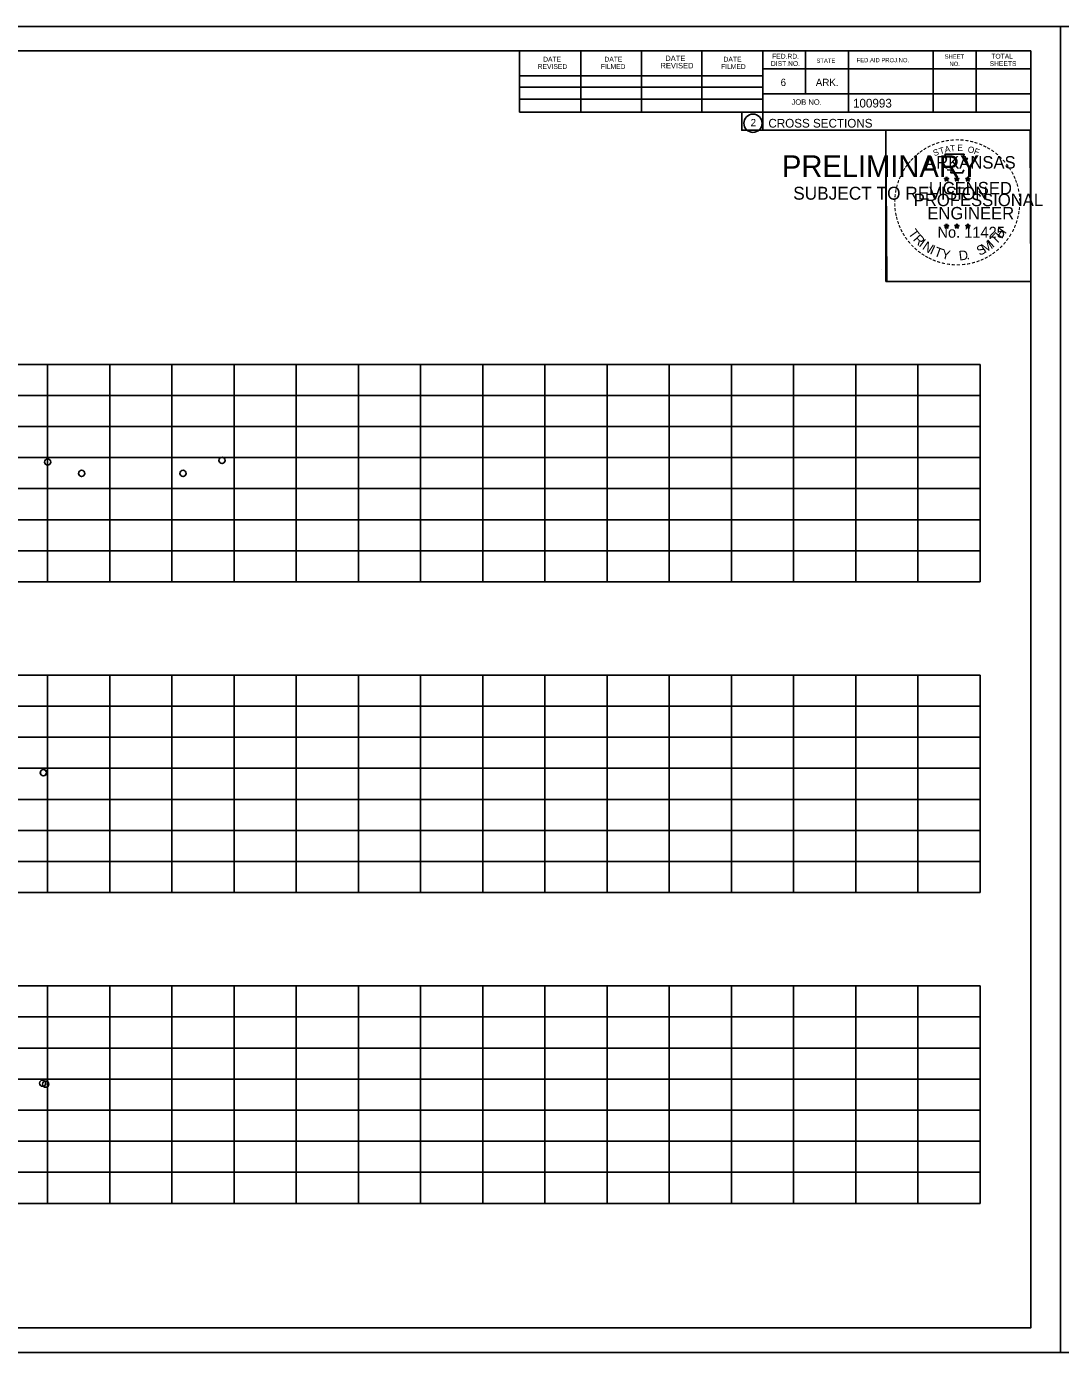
# Model space of a CAD drawing. Extents: x 4667 to 1632277, y -2100 to 724501.
# Drawn here: x 6136.1 to 6302.5, y -1963.8 to -1750.4 of the extents above; entities that cross this region are included whole.
import ezdxf

# ---------------------------------------------------------------- set-up
doc = ezdxf.new("R2010")
doc.units = 0
doc.layers.add('R_Grid', color=7, linetype='Continuous')
doc.layers.add('R_No Plot', color=7, linetype='Continuous')

msp = doc.modelspace()

# ---------------------------------------------------------------- linework, layer by layer
at = {"layer": 'R_Grid'}
for p, q in [((5989.52, -1804.78), (6289.52, -1804.78)), ((6139.52, -1839.78), (6139.52, -1804.78)), ((6149.52, -1839.78), (6149.52, -1804.78)), ((6159.52, -1839.78), (6159.52, -1804.78)), ((6169.52, -1839.78), (6169.52, -1804.78)), ((6179.52, -1839.78), (6179.52, -1804.78)), ((6189.52, -1839.78), (6189.52, -1804.78)), ((6199.52, -1839.78), (6199.52, -1804.78)), ((6209.52, -1839.78), (6209.52, -1804.78)), ((6219.52, -1839.78), (6219.52, -1804.78)), ((6229.52, -1839.78), (6229.52, -1804.78)), ((6239.52, -1839.78), (6239.52, -1804.78)), ((6249.52, -1839.78), (6249.52, -1804.78)), ((6259.52, -1839.78), (6259.52, -1804.78)), ((6269.52, -1839.78), (6269.52, -1804.78)), ((6279.52, -1839.78), (6279.52, -1804.78)), ((6289.52, -1839.78), (6289.52, -1804.78)), ((5989.52, -1809.78), (6289.52, -1809.78)), ((5989.52, -1814.78), (6289.52, -1814.78)), ((5989.52, -1819.78), (6289.52, -1819.78)), ((5989.52, -1824.78), (6289.52, -1824.78)), ((5989.52, -1829.78), (6289.52, -1829.78)), ((5989.52, -1834.78), (6289.52, -1834.78)), ((5989.52, -1839.78), (6289.52, -1839.78)), ((5989.52, -1854.78), (6289.52, -1854.78)), ((6139.52, -1889.78), (6139.52, -1854.78)), ((6149.52, -1889.78), (6149.52, -1854.78)), ((6159.52, -1889.78), (6159.52, -1854.78)), ((6169.52, -1889.78), (6169.52, -1854.78)), ((6179.52, -1889.78), (6179.52, -1854.78)), ((6189.52, -1889.78), (6189.52, -1854.78)), ((6199.52, -1889.78), (6199.52, -1854.78)), ((6209.52, -1889.78), (6209.52, -1854.78)), ((6219.52, -1889.78), (6219.52, -1854.78)), ((6229.52, -1889.78), (6229.52, -1854.78)), ((6239.52, -1889.78), (6239.52, -1854.78)), ((6249.52, -1889.78), (6249.52, -1854.78)), ((6259.52, -1889.78), (6259.52, -1854.78)), ((6269.52, -1889.78), (6269.52, -1854.78)), ((6279.52, -1889.78), (6279.52, -1854.78)), ((6289.52, -1889.78), (6289.52, -1854.78)), ((5989.52, -1859.78), (6289.52, -1859.78)), ((5989.52, -1864.78), (6289.52, -1864.78)), ((5989.52, -1869.78), (6289.52, -1869.78)), ((5989.52, -1874.78), (6289.52, -1874.78)), ((5989.52, -1879.78), (6289.52, -1879.78)), ((5989.52, -1884.78), (6289.52, -1884.78)), ((5989.52, -1889.78), (6289.52, -1889.78)), ((5989.52, -1904.78), (6289.52, -1904.78)), ((6139.52, -1939.78), (6139.52, -1904.78)), ((6149.52, -1939.78), (6149.52, -1904.78)), ((6159.52, -1939.78), (6159.52, -1904.78)), ((6169.52, -1939.78), (6169.52, -1904.78)), ((6179.52, -1939.78), (6179.52, -1904.78)), ((6189.52, -1939.78), (6189.52, -1904.78)), ((6199.52, -1939.78), (6199.52, -1904.78)), ((6209.52, -1939.78), (6209.52, -1904.78)), ((6219.52, -1939.78), (6219.52, -1904.78)), ((6229.52, -1939.78), (6229.52, -1904.78)), ((6239.52, -1939.78), (6239.52, -1904.78)), ((6249.52, -1939.78), (6249.52, -1904.78)), ((6259.52, -1939.78), (6259.52, -1904.78)), ((6269.52, -1939.78), (6269.52, -1904.78)), ((6279.52, -1939.78), (6279.52, -1904.78)), ((6289.52, -1939.78), (6289.52, -1904.78)), ((5989.52, -1909.78), (6289.52, -1909.78)), ((5989.52, -1914.78), (6289.52, -1914.78)), ((5989.52, -1919.78), (6289.52, -1919.78)), ((5989.52, -1924.78), (6289.52, -1924.78)), ((5989.52, -1929.78), (6289.52, -1929.78)), ((5989.52, -1934.78), (6289.52, -1934.78)), ((5989.52, -1939.78), (6289.52, -1939.78))]:
    msp.add_line(p, q, dxfattribs=at)
at = {"layer": 'R_No Plot'}
for p, q in [((5969.12, -1750.43), (6302.46, -1750.43)), ((5981.52, -1754.32), (6297.7, -1754.32)), ((6215.44, -1764.2), (6215.44, -1754.32)), ((6225.3, -1764.2), (6225.3, -1754.52)), ((6235.06, -1764.2), (6235.06, -1754.52)), ((6244.74, -1764.2), (6244.74, -1754.52)), ((6254.6, -1754.32), (6254.6, -1767.12)), ((6261.44, -1754.32), (6261.44, -1761.26)), ((6268.38, -1754.32), (6268.38, -1764.2)), ((6281.96, -1754.32), (6281.96, -1764.2)), ((6288.9, -1754.32), (6288.9, -1764.2)), ((6297.7, -1959.78), (6297.7, -1754.32)), ((6297.7, -1757.26), (6254.6, -1757.26)), ((6297.7, -1757.24), (6297.7, -1757.24)), ((6215.44, -1758.34), (6254.6, -1758.34)), ((6215.44, -1760.2), (6254.6, -1760.2)), ((6215.44, -1764.2), (6215.44, -1762.14)), ((6215.44, -1762.14), (6254.6, -1762.14)), ((6297.7, -1761.26), (6254.6, -1761.26)), ((6257.56, -1761.26), (6297.7, -1761.26)), ((6297.7, -1764.2), (6215.44, -1764.2)), ((6254.6, -1767.12), (6297.7, -1767.12)), ((6283.79, -1774.87), (6284.14, -1774.98)), ((6283.79, -1774.87), (6284.04, -1774.91)), ((6283.79, -1774.87), (6284.03, -1774.99)), ((6284.14, -1774.61), (6284.1, -1774.87)), ((6284.14, -1774.98), (6284.14, -1774.61)), ((6284.14, -1774.61), (6284.19, -1774.86)), ((6284.49, -1774.87), (6284.14, -1774.98)), ((6284.49, -1774.87), (6284.2, -1774.92)), ((6284.49, -1774.87), (6284.28, -1774.97)), ((6285.46, -1774.87), (6285.81, -1774.98)), ((6285.46, -1774.87), (6285.71, -1774.91)), ((6285.46, -1774.87), (6285.7, -1774.99)), ((6285.81, -1774.61), (6285.77, -1774.87)), ((6285.81, -1774.98), (6285.81, -1774.61)), ((6285.81, -1774.61), (6285.86, -1774.86)), ((6286.16, -1774.87), (6285.81, -1774.98)), ((6286.16, -1774.87), (6285.87, -1774.92)), ((6286.16, -1774.87), (6285.95, -1774.97)), ((6287.22, -1774.88), (6287.57, -1774.99)), ((6287.22, -1774.88), (6287.48, -1774.92)), ((6287.22, -1774.88), (6287.46, -1775)), ((6287.57, -1774.63), (6287.53, -1774.88)), ((6287.57, -1774.99), (6287.57, -1774.63)), ((6287.57, -1774.63), (6287.62, -1774.88)), ((6287.92, -1774.88), (6287.57, -1774.99)), ((6287.92, -1774.88), (6287.63, -1774.93)), ((6287.92, -1774.88), (6287.72, -1774.98)), ((6283.92, -1775.28), (6284.14, -1774.98)), ((6283.92, -1775.28), (6284.05, -1775.03)), ((6283.92, -1775.28), (6284.14, -1775.06)), ((6284.35, -1775.28), (6284.14, -1774.98)), ((6284.35, -1775.28), (6284.14, -1775.06)), ((6284.35, -1775.28), (6284.21, -1774.98)), ((6285.59, -1775.28), (6285.81, -1774.98)), ((6285.59, -1775.28), (6285.72, -1775.03)), ((6285.59, -1775.28), (6285.81, -1775.06)), ((6286.02, -1775.28), (6285.81, -1774.98)), ((6286.02, -1775.28), (6285.81, -1775.06)), ((6286.02, -1775.28), (6285.88, -1774.98)), ((6287.36, -1775.29), (6287.57, -1774.99)), ((6287.36, -1775.29), (6287.48, -1775.04)), ((6287.36, -1775.29), (6287.57, -1775.07)), ((6287.79, -1775.29), (6287.57, -1774.99)), ((6287.79, -1775.29), (6287.57, -1775.07)), ((6287.79, -1775.29), (6287.65, -1775)), ((6283.79, -1782.44), (6284.13, -1782.55)), ((6283.79, -1782.44), (6284.04, -1782.49)), ((6283.79, -1782.44), (6284.02, -1782.56)), ((6283.92, -1782.85), (6284.13, -1782.55)), ((6283.92, -1782.85), (6284.04, -1782.6)), ((6283.92, -1782.85), (6284.13, -1782.63)), ((6284.13, -1782.19), (6284.09, -1782.44)), ((6284.13, -1782.55), (6284.13, -1782.19)), ((6284.13, -1782.19), (6284.18, -1782.44)), ((6284.48, -1782.44), (6284.13, -1782.55)), ((6284.35, -1782.85), (6284.13, -1782.55)), ((6284.35, -1782.85), (6284.13, -1782.63)), ((6284.48, -1782.44), (6284.2, -1782.49)), ((6284.35, -1782.85), (6284.21, -1782.56)), ((6284.48, -1782.44), (6284.28, -1782.54)), ((6285.45, -1782.44), (6285.8, -1782.55)), ((6285.45, -1782.44), (6285.71, -1782.49)), ((6285.45, -1782.44), (6285.69, -1782.56)), ((6285.59, -1782.85), (6285.8, -1782.55)), ((6285.59, -1782.85), (6285.71, -1782.6)), ((6285.59, -1782.85), (6285.8, -1782.63)), ((6285.8, -1782.19), (6285.76, -1782.44)), ((6285.8, -1782.55), (6285.8, -1782.19)), ((6285.8, -1782.19), (6285.85, -1782.44)), ((6286.15, -1782.44), (6285.8, -1782.55)), ((6286.02, -1782.85), (6285.8, -1782.55)), ((6286.02, -1782.85), (6285.8, -1782.63)), ((6286.15, -1782.44), (6285.86, -1782.49)), ((6286.02, -1782.85), (6285.88, -1782.56)), ((6286.15, -1782.44), (6285.95, -1782.54)), ((6287.22, -1782.45), (6287.57, -1782.56)), ((6287.22, -1782.45), (6287.47, -1782.5)), ((6287.22, -1782.45), (6287.46, -1782.57)), ((6287.35, -1782.86), (6287.57, -1782.56)), ((6287.35, -1782.86), (6287.48, -1782.61)), ((6287.35, -1782.86), (6287.57, -1782.64)), ((6287.57, -1782.2), (6287.53, -1782.45)), ((6287.57, -1782.56), (6287.57, -1782.2)), ((6287.57, -1782.2), (6287.62, -1782.45)), ((6287.92, -1782.45), (6287.57, -1782.56)), ((6287.78, -1782.86), (6287.57, -1782.56)), ((6287.78, -1782.86), (6287.57, -1782.64)), ((6287.92, -1782.45), (6287.63, -1782.5)), ((6287.78, -1782.86), (6287.65, -1782.57)), ((6287.92, -1782.45), (6287.71, -1782.55)), ((6273.74, -1789.58), (6273.74, -1789.58)), ((6297.7, -1959.78), (5981.52, -1959.78)), ((5969.12, -1963.76), (6302.46, -1963.76))]:
    msp.add_line(p, q, dxfattribs=at)
for points in [[(5969.12, -1750.43), (6302.46, -1750.43), (6302.46, -1963.77), (5969.12, -1963.77)], [(6302.46, -1750.43), (6635.8, -1750.43), (6635.8, -1963.77), (6302.46, -1963.77)], [(6215.44, -1754.32), (6215.44, -1764.2), (6251.18, -1764.2), (6251.18, -1767.12), (6274.38, -1767.12), (6274.38, -1791.45), (6297.7, -1791.45), (6297.7, -1959.78), (5981.52, -1959.78), (5981.52, -1754.32)], [(6274.38, -1767.12), (6297.58, -1767.12), (6297.7, -1791.45), (6274.5, -1791.45)]]:
    msp.add_lwpolyline(points, close=True, dxfattribs=at)
for points in [[(6283.83, -1770.99), (6284.1, -1771.82)], [(6287.34, -1771.91), (6287.48, -1771.63), (6286.8, -1771.65), (6286.95, -1770.99), (6283.83, -1770.99)], [(6284.14, -1774.61), (6284.35, -1775.28), (6283.79, -1774.87), (6284.49, -1774.87), (6283.92, -1775.28), (6284.14, -1774.61)], [(6284.32, -1773.41), (6284.32, -1773.5), (6284.89, -1773.52), (6284.83, -1773.99), (6286.7, -1773.99), (6286.9, -1773.46)], [(6285.81, -1774.61), (6286.02, -1775.28), (6285.46, -1774.87), (6286.16, -1774.87), (6285.59, -1775.28), (6285.81, -1774.61)], [(6287.57, -1774.63), (6287.79, -1775.29), (6287.22, -1774.88), (6287.92, -1774.88), (6287.36, -1775.29), (6287.57, -1774.63)], [(6284.13, -1782.19), (6284.35, -1782.85), (6283.79, -1782.44), (6284.48, -1782.44), (6283.92, -1782.85), (6284.13, -1782.19)], [(6285.8, -1782.19), (6286.02, -1782.85), (6285.45, -1782.44), (6286.15, -1782.44), (6285.59, -1782.85), (6285.8, -1782.19)], [(6287.57, -1782.2), (6287.78, -1782.86), (6287.22, -1782.45), (6287.92, -1782.45), (6287.35, -1782.86), (6287.57, -1782.2)]]:
    msp.add_lwpolyline(points, dxfattribs=at)
for centre, radius in [((6252.99, -1765.99), 1.47), ((6284.14, -1774.98), 0.172), ((6284.14, -1774.98), 0.145), ((6284.14, -1774.98), 0.116), ((6284.14, -1774.98), 0.0991), ((6284.14, -1774.98), 0.0747), ((6284.14, -1774.98), 0.0495), ((6284.14, -1774.98), 0.0296), ((6285.81, -1774.98), 0.172), ((6285.81, -1774.98), 0.145), ((6285.81, -1774.98), 0.116), ((6285.81, -1774.98), 0.0991), ((6285.81, -1774.98), 0.0747), ((6285.81, -1774.98), 0.0495), ((6285.81, -1774.98), 0.0296), ((6287.57, -1774.99), 0.172), ((6287.57, -1774.99), 0.145), ((6287.57, -1774.99), 0.116), ((6287.57, -1774.99), 0.0991), ((6287.57, -1774.99), 0.0747), ((6287.57, -1774.99), 0.0495), ((6287.57, -1774.99), 0.0296), ((6284.13, -1782.55), 0.172), ((6284.13, -1782.55), 0.145), ((6284.13, -1782.55), 0.116), ((6284.13, -1782.55), 0.0991), ((6284.13, -1782.55), 0.0747), ((6284.13, -1782.55), 0.0495), ((6284.13, -1782.55), 0.0296), ((6285.8, -1782.55), 0.172), ((6285.8, -1782.55), 0.145), ((6285.8, -1782.55), 0.116), ((6285.8, -1782.55), 0.0991), ((6285.8, -1782.55), 0.0747), ((6285.8, -1782.55), 0.0495), ((6285.8, -1782.55), 0.0296), ((6287.57, -1782.56), 0.172), ((6287.57, -1782.56), 0.145), ((6287.57, -1782.56), 0.116), ((6287.57, -1782.56), 0.0991), ((6287.57, -1782.56), 0.0747), ((6287.57, -1782.56), 0.0495), ((6287.57, -1782.56), 0.0296), ((6167.58, -1820.24), 0.5), ((6139.52, -1820.51), 0.5), ((6144.98, -1822.33), 0.5), ((6161.31, -1822.33), 0.5), ((6138.82, -1870.49), 0.5), ((6138.86, -1870.47), 0.5), ((6138.86, -1870.47), 0.5), ((6138.7, -1920.44), 0.5), ((6139.19, -1920.6), 0.5)]:
    msp.add_circle(centre, radius, dxfattribs=at)

# ---------------------------------------------------------------- texts
for s, height, rotation, p in [('DATE', 0.782, 360, (6219.24, -1756.08)), ('DATE', 0.782, 360, (6229.1, -1756.08)), ('DATE', 0.879, 360, (6238.88, -1755.98)), ('DATE', 0.782, 360, (6248.26, -1756.08)), ('FED.RD.', 0.782, 360, (6256.08, -1755.6)), ('STATE', 0.684, 360, (6263.2, -1756.28)), ('FED.AID PROJ.NO.', 0.684, 360, (6269.66, -1756.18)), ('SHEET', 0.684, 360, (6283.82, -1755.6)), ('TOTAL', 0.782, 360, (6291.34, -1755.6)), ('REVISED', 0.782, 360, (6218.36, -1757.26)), ('FILMED', 0.782, 360, (6228.52, -1757.26)), ('REVISED', 0.879, 360, (6238.1, -1757.16)), ('FILMED', 0.782, 360, (6247.86, -1757.26)), ('DIST.NO.', 0.782, 360, (6255.88, -1756.78)), ('NO.', 0.684, 360, (6284.6, -1756.78)), ('SHEETS', 0.782, 360, (6291.06, -1756.78)), ('6', 1.17, 360, (6257.44, -1760)), ('ARK.', 1.172, 360, (6263.1, -1760)), ('JOB NO.', 0.879, 360, (6259.2, -1763.02)), ('100993', 1.4, 360, (6269.08, -1763.46)), ('2', 1.17, 360, (6252.61, -1766.47)), ('CROSS SECTIONS', 1.4, 360, (6255.47, -1766.69)), ('-', 1.6, 0.1862, (6285.51, -1769.28)), ('-', 1.6, 38.9507, (6279.66, -1771.59)), ('-', 1.6, 36.2317, (6280.14, -1771.21)), ('-', 1.6, 34.0636, (6280.71, -1770.82)), ('-', 1.6, 28.7918, (6281.31, -1770.45)), ('-', 1.6, 24.3072, (6281.94, -1770.13)), ('S', 1, 21.594, (6282.18, -1771.31)), ('-', 1.6, 19.1761, (6282.58, -1769.86)), ('T', 1, 16.4036, (6283.1, -1770.98)), ('-', 1.6, 13.6301, (6283.33, -1769.62)), ('A', 1, 11.2132, (6283.92, -1770.73)), ('-', 1.6, 10.2193, (6284.01, -1769.46)), ('T', 1, 6.0228, (6284.77, -1770.56)), ('-', 1.6, 5.8968, (6284.73, -1769.35)), ('E', 1, 0.8323, (6285.88, -1770.45)), ('-', 1.6, 357.743, (6286.23, -1769.29)), ('-', 1.6, 352.1617, (6286.97, -1769.35)), ('O', 1, 350.4515, (6287.48, -1770.66)), ('-', 1.6, 347.2049, (6287.69, -1769.46)), ('F', 1, 340.0707, (6288.44, -1770.89)), ('-', 1.6, 342.3362, (6288.33, -1769.62)), ('-', 1.6, 337.8551, (6289.06, -1769.84)), ('-', 1.6, 334.1211, (6289.69, -1770.11)), ('-', 1.6, 329.6409, (6290.27, -1770.39)), ('-', 1.6, 325.8627, (6290.92, -1770.75)), ('-', 1.6, 320.5297, (6291.53, -1771.18)), ('PRELIMINARY', 3.5, 360, (6257.66, -1774.66)), ('DWB', 0.01, 360, (6258.4, -1772.81)), ('-', 1.6, 54.2325, (6277.96, -1773.54)), ('-', 1.6, 50.6142, (6278.38, -1772.97)), ('-', 1.6, 48.423, (6278.78, -1772.49)), ('-', 1.6, 42.9622, (6279.23, -1772.01)), ('ARKANSAS', 2, 360, (6280.68, -1773.28)), ('-', 1.6, 315.5786, (6292.12, -1771.67)), ('-', 1.6, 309.8797, (6292.69, -1772.22)), ('-', 1.6, 306.6522, (6293.22, -1772.82)), ('-', 1.6, 67.7743, (6277.07, -1775.29)), ('-', 1.6, 62.8713, (6277.32, -1774.68)), ('-', 1.6, 58.0706, (6277.64, -1774.07)), ('-', 1.4, 303.6753, (6293.7, -1773.39)), ('-', 1.6, 299.6684, (6294.02, -1773.99)), ('-', 1.6, 294.6628, (6294.35, -1774.61)), ('SUBJECT TO REVISION', 2.0751, 360, (6259.46, -1778.29)), ('-', 1.6, 81.2013, (6276.52, -1777.35)), ('-', 1.6, 75.461, (6276.65, -1776.64)), ('-', 1.6, 72.3945, (6276.85, -1775.92)), ('LICENSED', 2, 360, (6281.28, -1777.43)), ('DWB', 0.01, 360, (6284.13, -1774.98)), ('DWB', 0.01, 360, (6285.8, -1774.98)), ('DWB', 0.01, 360, (6287.56, -1774.99)), ('-', 1.6, 290.5728, (6294.6, -1775.18)), ('-', 1.6, 285.1233, (6294.84, -1775.76)), ('-', 1.6, 280.5493, (6295.04, -1776.51)), ('-', 1.6, 94.1959, (6276.45, -1779.47)), ('-', 1.6, 89.0622, (6276.42, -1778.74)), ('-', 1.6, 85.1863, (6276.44, -1778.04)), ('PROFESSIONAL', 2, 360, (6278.86, -1779.33)), ('-', 1.6, 276.5962, (6295.2, -1777.27)), ('-', 1.6, 274.3301, (6295.26, -1778)), ('-', 1.6, 269.9407, (6295.29, -1778.63)), ('-', 1.6, 98.9479, (6276.52, -1780.13)), ('-', 1.6, 101.7149, (6276.66, -1780.87)), ('-', 1.6, 105.4578, (6276.82, -1781.46)), ('ENGINEER', 2, 360, (6281.04, -1781.46)), ('-', 1.6, 255.7626, (6295.09, -1780.63)), ('-', 1.6, 260.9953, (6295.2, -1779.95)), ('-', 1.6, 263.5172, (6295.28, -1779.29)), ('-', 1.6, 109.0874, (6277.04, -1782.09)), ('-', 1.6, 114.0643, (6277.29, -1782.69)), ('-', 1.6, 115.7289, (6277.59, -1783.31)), ('T', 1.54, 306.0406, (6277.89, -1783.71)), ('No. 11425', 1.757, 360, (6282.67, -1784.41)), ('DWB', 0.01, 360, (6284.12, -1782.56)), ('DWB', 0.01, 360, (6285.79, -1782.56)), ('DWB', 0.01, 360, (6287.56, -1782.57)), ('H', 1.54, 54.6088, (6293.01, -1784.68)), ('-', 1.6, 244.6197, (6294.43, -1782.65)), ('-', 1.6, 247.8887, (6294.69, -1782.02)), ('-', 1.6, 252.8681, (6294.91, -1781.35)), ('-', 1.6, 120.4471, (6277.95, -1783.89)), ('-', 1.6, 125.8934, (6278.35, -1784.45)), ('-', 1.6, 130.7181, (6278.82, -1785)), ('-', 1.6, 134.2238, (6279.33, -1785.55)), ('R', 1.54, 314.005, (6278.66, -1784.76)), ('I', 1.54, 321.9694, (6279.56, -1785.69)), ('N', 1.54, 326.5002, (6280.12, -1786.16)), ('I', 1.54, 335.3603, (6281.33, -1786.95)), ('S', 1.54, 26.9312, (6289.44, -1787.35)), ('M', 1.54, 32.6563, (6290.28, -1786.95)), ('I', 1.54, 42.1136, (6291.56, -1786.1)), ('T', 1.54, 46.6444, (6292.12, -1785.62)), ('-', 1.6, 225.7653, (6292.72, -1785.18)), ('-', 1.6, 231.2538, (6293.2, -1784.62)), ('-', 1.6, 233.8452, (6293.63, -1784.05)), ('-', 1.6, 239.0712, (6294.03, -1783.4)), ('-', 1.6, 138.9338, (6279.86, -1786.01)), ('-', 1.6, 144.6463, (6280.41, -1786.42)), ('-', 1.6, 148.0898, (6280.98, -1786.79)), ('-', 1.6, 151.5704, (6281.55, -1787.12)), ('-', 1.6, 154.6002, (6282.08, -1787.36)), ('T', 1.54, 339.8912, (6281.99, -1787.28)), ('Y', 1.54, 347.8556, (6283.21, -1787.72)), ('D', 1.54, 6.3969, (6286.19, -1788.08)), ('.', 1.54, 13.7642, (6287.39, -1787.95)), ('-', 1.6, 204.2516, (6289.94, -1787.22)), ('-', 1.6, 207.3568, (6290.56, -1786.9)), ('-', 1.6, 212.2491, (6291.12, -1786.55)), ('-', 1.6, 215.7363, (6291.65, -1786.16)), ('-', 1.6, 221.0851, (6292.2, -1785.69)), ('-', 1.6, 158.5612, (6282.7, -1787.62)), ('-', 1.6, 162.7983, (6283.39, -1787.83)), ('-', 1.6, 167.5555, (6284.1, -1787.99)), ('-', 1.6, 173.1155, (6284.87, -1788.1)), ('-', 1.6, 176.5183, (6285.62, -1788.16)), ('-', 1.6, 181.5918, (6286.37, -1788.14)), ('-', 1.6, 185.8167, (6287.18, -1788.06)), ('-', 1.6, 191.2858, (6287.91, -1787.93)), ('-', 1.6, 195.4743, (6288.64, -1787.73)), ('-', 1.6, 200.7184, (6289.32, -1787.49))]:
    msp.add_text(s, height=height, rotation=rotation, dxfattribs=at).set_placement(p)

doc.saveas('drawing.dxf')
